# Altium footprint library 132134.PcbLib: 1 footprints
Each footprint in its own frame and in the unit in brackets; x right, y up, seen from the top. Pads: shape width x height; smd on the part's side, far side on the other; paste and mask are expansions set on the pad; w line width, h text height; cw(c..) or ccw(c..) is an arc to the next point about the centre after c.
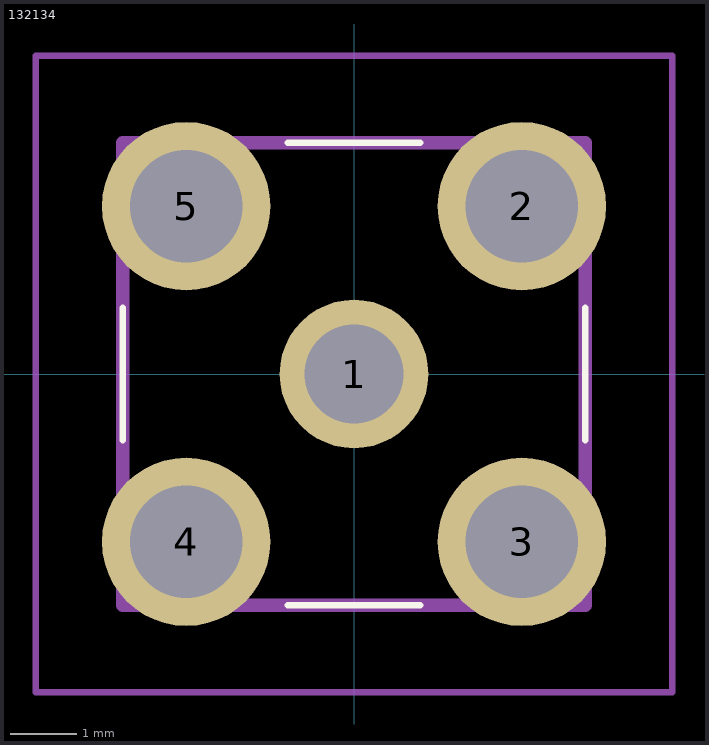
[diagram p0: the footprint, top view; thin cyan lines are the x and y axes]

## 132134 [mm]
pads (5):
  round 2.25 hole 1.5: 1(0,0)
  round 2.55 hole 1.7: 2(2.54,2.54) 3(2.54,-2.54) 4(-2.54,-2.54) 5(-2.54,2.54)
Top Overlay:
  lines w0.1: -3.5,-1 -3.5,1 ; -3.5,-1 -3.5,-1 ; -3.5,-1 -3.5,1 ; -3.5,1 -3.5,1 ; -1,-3.5 1,-3.5 ; -1,-3.5 1,-3.5 ; -1,-3.5 -1,-3.5 ; -1,3.5 1,3.5 ; -1,3.5 -1,3.5 ; -1,3.5 1,3.5 ; 1,-3.5 1,-3.5 ; 1,3.5 1,3.5 ; 3.5,-1 3.5,-1 ; 3.5,-1 3.5,1 ; 3.5,-1 3.5,1 ; 3.5,1 3.5,1
Mechanical 15:
  lines w0.2: -3.5,-3.5 3.5,-3.5 3.5,3.5 -3.5,3.5 -3.5,-3.5
Mechanical 20:
  lines w0.1: -4.815,-4.815 4.815,-4.815 4.815,4.815 -4.815,4.815 -4.815,-4.815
